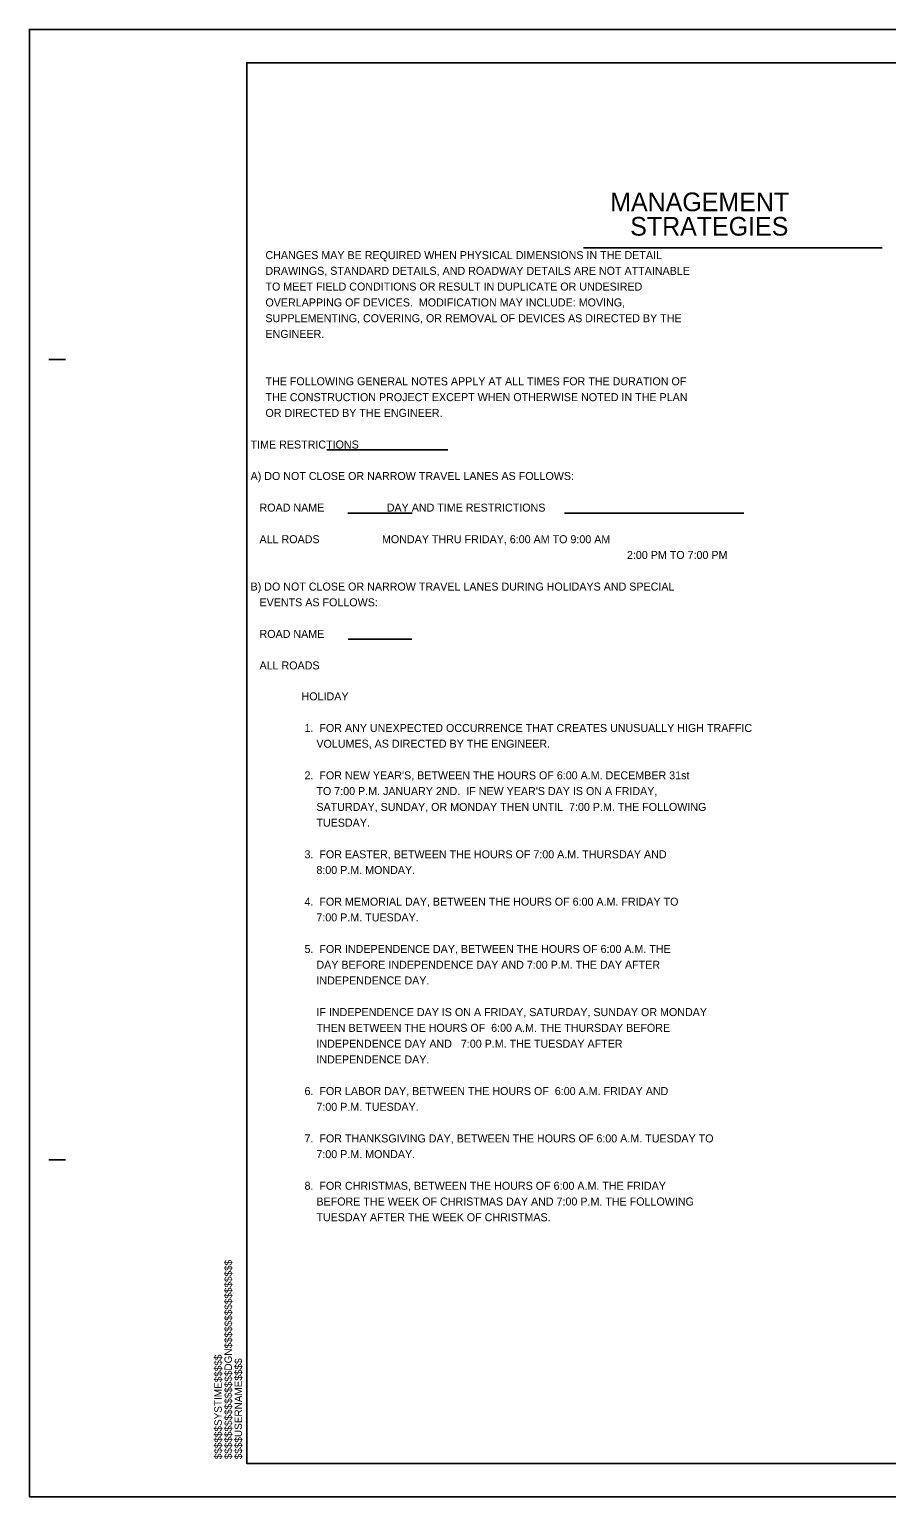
# Model space of a CAD drawing. Extents: x 762655 to 770567, y 650864 to 655190.
# Drawn here: x 768879 to 769522, y 654090 to 655190 of the extents above; entities that cross this region are included whole.
import ezdxf

# ---------------------------------------------------------------- set-up
doc = ezdxf.new("R2010")
doc.units = 0
for name, color, linetype in [('Default', 7, 'Continuous'), ('DEV BORDER CELL', 7, 'Continuous'), ('DEV TRANSPORTATION OPERATIONS PLAN SHEET', 7, 'Continuous'), ('Text', 7, 'Continuous')]:
    doc.layers.add(name, color=color, linetype=linetype)

msp = doc.modelspace()

# ---------------------------------------------------------------- linework, layer by layer
at = {"layer": 'Default'}
for p, q in [((769102.1, 654874.6), (769192.8, 654874.6)), ((769117.8, 654827.2), (769166, 654827.2)), ((769280.3, 654827.2), (769414.7, 654827.2)), ((769118, 654732.6), (769165.9, 654732.6))]:
    msp.add_line(p, q, dxfattribs=at)
at = {"layer": 'DEV BORDER CELL'}
msp.add_line((769294.5, 655026), (769518.6, 655026), dxfattribs=at)
at = {"layer": 'DEV TRANSPORTATION OPERATIONS PLAN SHEET'}
for p, q in [((769043, 655164.8), (769043, 655164.8)), ((768893.5, 654942.3), (768906, 654942.3)), ((768893.5, 654342.3), (768906, 654342.3)), ((769042, 654114.8), (769042, 654114.8))]:
    msp.add_line(p, q, dxfattribs=at)
msp.add_lwpolyline([(770542, 655164.8), (769042, 655164.8), (769042, 654114.8), (770542, 654114.8)], close=True, dxfattribs=at)
at = {"layer": 'Text'}
msp.add_lwpolyline([(768879, 654089.8), (770567, 654089.8), (770567, 655189.8), (768879, 655189.8)], close=True, dxfattribs=at)

# ---------------------------------------------------------------- texts
at = {"layer": 'DEV TRANSPORTATION OPERATIONS PLAN SHEET'}
for s, p in [('MANAGEMENT ', (769314.6, 655053.5)), ('STRATEGIES', (769329.6, 655035.2))]:
    msp.add_text(s, height=14, dxfattribs=at).set_placement(p)
for s, p in [('$$$$$$$$$$$$$$$$DGN$$$$$$$$$$$$$$$$', (769030.9, 654117.9)), ('$$$$$$SYSTIME$$$$$', (769023.3, 654117.9)), ('$$$$USERNAME$$$$', (769038.5, 654117.9))]:
    msp.add_text(s, height=5.584, rotation=90, dxfattribs=at).set_placement(p)
at = {"layer": 'Text'}
for s, p in [('            CHANGES MAY BE REQUIRED WHEN PHYSICAL DIMENSIONS IN THE DETAIL ', (769029.3, 655017.6)), ('            DRAWINGS, STANDARD DETAILS, AND ROADWAY DETAILS ARE NOT ATTAINABLE ', (769029.3, 655005.8)), ('            TO MEET FIELD CONDITIONS OR RESULT IN DUPLICATE OR UNDESIRED ', (769029.3, 654994)), ('            OVERLAPPING OF DEVICES.  MODIFICATION MAY INCLUDE: MOVING, ', (769029.3, 654982.1)), ('            SUPPLEMENTING, COVERING, OR REMOVAL OF DEVICES AS DIRECTED BY THE ', (769029.3, 654970.3)), ('            ENGINEER.  ', (769029.3, 654958.5)), ('            THE FOLLOWING GENERAL NOTES APPLY AT ALL TIMES FOR THE DURATION OF', (769029.3, 654923)), ('            THE CONSTRUCTION PROJECT EXCEPT WHEN OTHERWISE NOTED IN THE PLAN', (769029.3, 654911.1)), ('            OR DIRECTED BY THE ENGINEER.', (769029.3, 654899.3)), ('       TIME RESTRICTIONS ', (769029.3, 654875.6)), ('       A) DO NOT CLOSE OR NARROW TRAVEL LANES AS FOLLOWS:', (769029.3, 654852)), ('          ROAD NAME                     DAY AND TIME RESTRICTIONS', (769029.3, 654828.3)), ('          ALL ROADS                     MONDAY THRU FRIDAY, 6:00 AM TO 9:00 AM                 ', (769029.3, 654804.6)), ('        2:00 PM TO 7:00 PM', (769309.3, 654792.8)), ('       B) DO NOT CLOSE OR NARROW TRAVEL LANES DURING HOLIDAYS AND SPECIAL', (769029.3, 654769.1)), ('          EVENTS AS FOLLOWS:', (769029.3, 654757.3)), ('          ROAD NAME ', (769029.3, 654733.6)), ('          ALL ROADS ', (769029.3, 654710)), ('           HOLIDAY', (769058.6, 654686.8)), ('            1.  FOR ANY UNEXPECTED OCCURRENCE THAT CREATES UNUSUALLY HIGH TRAFFIC ', (769058.6, 654663.1)), ('                VOLUMES, AS DIRECTED BY THE ENGINEER.', (769058.6, 654651.3)), ("            2.  FOR NEW YEAR'S, BETWEEN THE HOURS OF 6:00 A.M. DECEMBER 31st", (769058.6, 654627.6)), ("                TO 7:00 P.M. JANUARY 2ND.  IF NEW YEAR'S DAY IS ON A FRIDAY,", (769058.6, 654615.8)), ('                SATURDAY, SUNDAY, OR MONDAY THEN UNTIL  7:00 P.M. THE FOLLOWING ', (769058.6, 654603.9)), ('                TUESDAY.  ', (769058.6, 654592.1)), ('            3.  FOR EASTER, BETWEEN THE HOURS OF 7:00 A.M. THURSDAY AND', (769058.6, 654568.4)), ('                8:00 P.M. MONDAY.', (769058.6, 654556.6)), ('            4.  FOR MEMORIAL DAY, BETWEEN THE HOURS OF 6:00 A.M. FRIDAY TO', (769058.6, 654532.9)), ('                7:00 P.M. TUESDAY.', (769058.6, 654521.1)), ('            5.  FOR INDEPENDENCE DAY, BETWEEN THE HOURS OF 6:00 A.M. THE', (769058.6, 654497.4)), ('                DAY BEFORE INDEPENDENCE DAY AND 7:00 P.M. THE DAY AFTER', (769058.6, 654485.6)), ('                INDEPENDENCE DAY.', (769058.6, 654473.8)), ('                IF INDEPENDENCE DAY IS ON A FRIDAY, SATURDAY, SUNDAY OR MONDAY  ', (769058.6, 654450.1)), ('                THEN BETWEEN THE HOURS OF  6:00 A.M. THE THURSDAY BEFORE ', (769058.6, 654438.3)), ('                INDEPENDENCE DAY AND   7:00 P.M. THE TUESDAY AFTER', (769058.6, 654426.4)), ('                INDEPENDENCE DAY.   ', (769058.6, 654414.6)), ('            6.  FOR LABOR DAY, BETWEEN THE HOURS OF  6:00 A.M. FRIDAY AND', (769058.6, 654390.9)), ('                7:00 P.M. TUESDAY.', (769058.6, 654379.1)), ('            7.  FOR THANKSGIVING DAY, BETWEEN THE HOURS OF 6:00 A.M. TUESDAY TO', (769058.6, 654355.4)), ('                7:00 P.M. MONDAY.', (769058.6, 654343.6)), ('            8.  FOR CHRISTMAS, BETWEEN THE HOURS OF 6:00 A.M. THE FRIDAY', (769058.6, 654319.9)), ('                BEFORE THE WEEK OF CHRISTMAS DAY AND 7:00 P.M. THE FOLLOWING', (769058.6, 654308.1)), ('                TUESDAY AFTER THE WEEK OF CHRISTMAS.', (769058.6, 654296.3))]:
    msp.add_text(s, height=6, dxfattribs=at).set_placement(p)

doc.saveas('drawing.dxf')
